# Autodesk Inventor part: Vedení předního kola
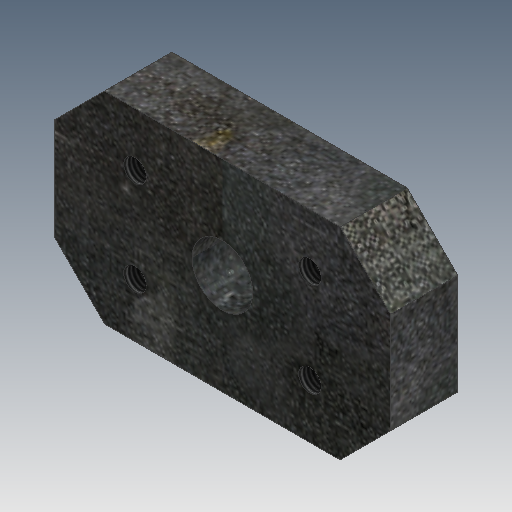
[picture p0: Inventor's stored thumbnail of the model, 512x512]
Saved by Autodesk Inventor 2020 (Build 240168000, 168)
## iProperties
Created: 2025-03
Part Number: Vedení předního kola
Material: Ocel
Document SubType Name: Modeling
Designer: doma
Density: 7.85 g/cm^3
Appearance: Plech
Mass: 793.227 g
Surface Area: 196.191 cm^2
Volume: 101.048 cm^3
Author: doma
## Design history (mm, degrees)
sketch "Náčrt1"
  geometry: L1 (0, 0)-(100, 0); L2 (100, 0)-(100, 60); L3 (100, 60)-(0, 60); L4 (0, 60)-(0, 0)
  constraints: 8 end point, 2 parallel, 1 horizontal, 1 perpendicular
  dimensions: "d0" = 100 distance of L3.end L2.end; "d1" = 60 distance of L2.end L1.end
extrude "Vysunutí1" new body sketch "Náčrt1" distance "d2" = 20; taper "d3" = 0 deg
chamfer "Zkosení1" distance "d4" = 15; stored, may be unused: second distance "d5" = 2, angle "d6" = 45 deg
sketch "Náčrt2"
  geometry: L1 (85, 60)-(15, 60) reference; L2 (100, 15)-(100, 45) reference; L3 (24, 16)-(76, 16); L4 (76, 16)-(76, 44); L5 (76, 44)-(24, 44); L6 (24, 44)-(24, 16); L7 (24, 16)-(76, 44); L8 (76, 16)-(24, 44); 6 further points
  constraints: 12 end point, 4 coincident, 2 midpoint, 2 parallel, 1 horizontal, 1 perpendicular
  dimensions: "d9" = 52 distance of L5.end L4.end; "d10" = 28 distance of L4.end L3.end
hole "Díra1" sketch "Náčrt2" diameter "d11" = 6.647; stored, may be unused: countersink angle "d15" = 90 deg, drill point angle "d17" = 118 deg; dims "d12" = 16, "d13" = 4, "d14" = 2, "d16" = 22.2
hole "Díra2" sketch "Náčrt2" diameter "d18" = 18; stored, may be unused: countersink angle "d22" = 90 deg, drill point angle "d24" = 118 deg; dims "d19" = 32, "d20" = 4, "d21" = 2, "d23" = 41.3
sketch "Náčrt3"
  geometry: L1 (0, 0)-(0, 30) reference; L2 (20, 0)-(20, 30) reference; L3 (10, 30)-(10, 0); L4 (0, 15)-(20, 15); 2 further points
  constraints: 4 end point, 3 midpoint, 1 vertical
hole "Díra3" sketch "Náčrt3" at (10, 15) diameter "d25" = 10.106; stored, may be unused: countersink angle "d29" = 90 deg, drill point angle "d31" = 118 deg; dims "d26" = 24, "d27" = 4, "d28" = 2, "d30" = 25
node "Těleso1"
